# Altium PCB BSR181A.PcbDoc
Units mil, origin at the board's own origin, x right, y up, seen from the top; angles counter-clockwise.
Board outline 2710.5 x 1796.5 mil, 4 copper layers (Top Layer, Signal Layer 1, Signal Layer 2, Bottom Layer), stack 60.434 mil thick; 45 components, 12 nets, 61 pads, 44 vias.
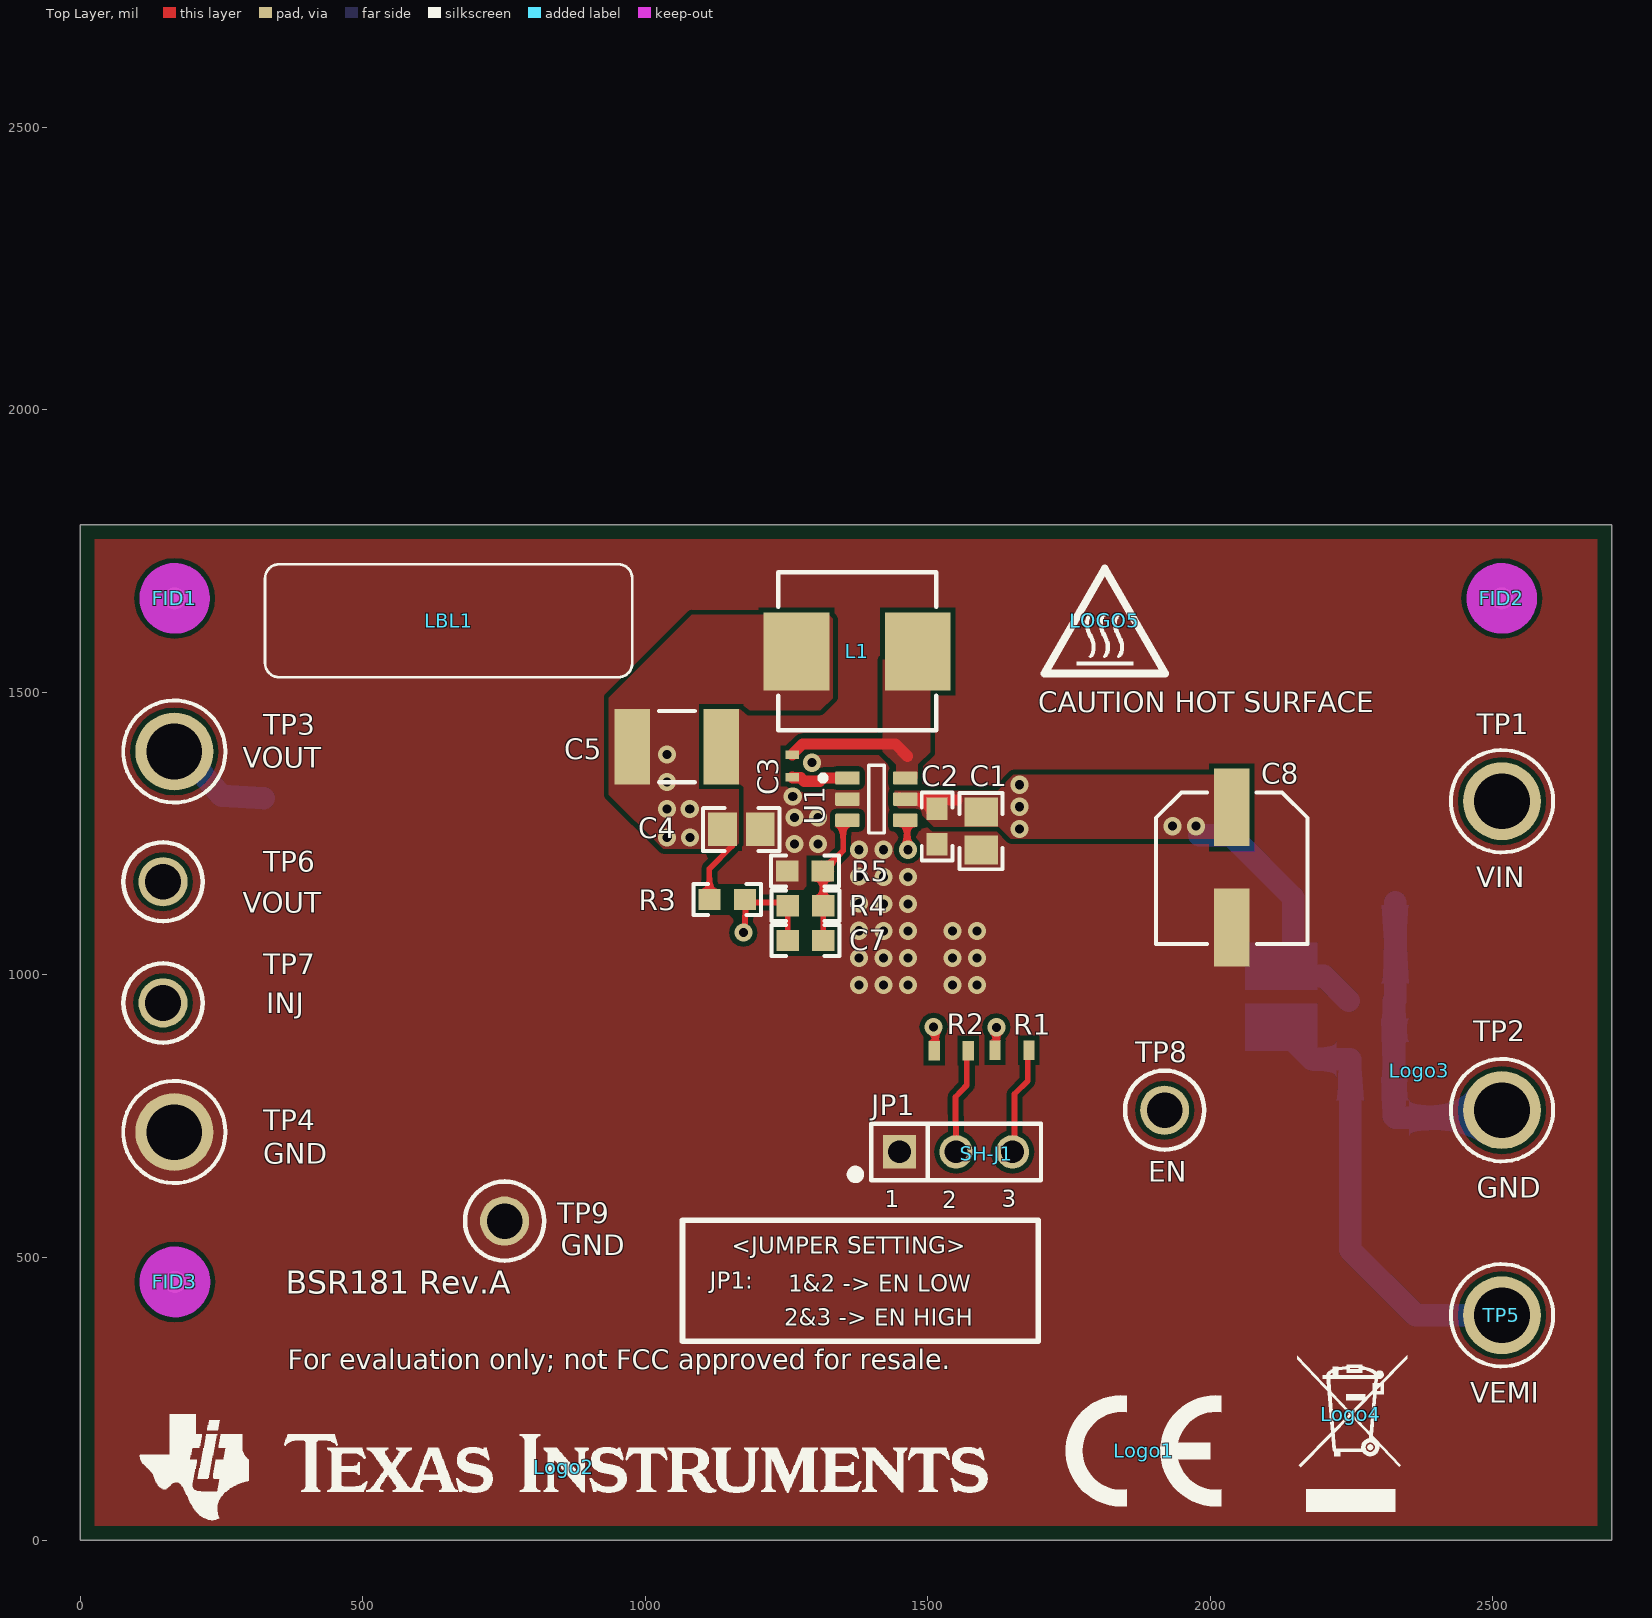
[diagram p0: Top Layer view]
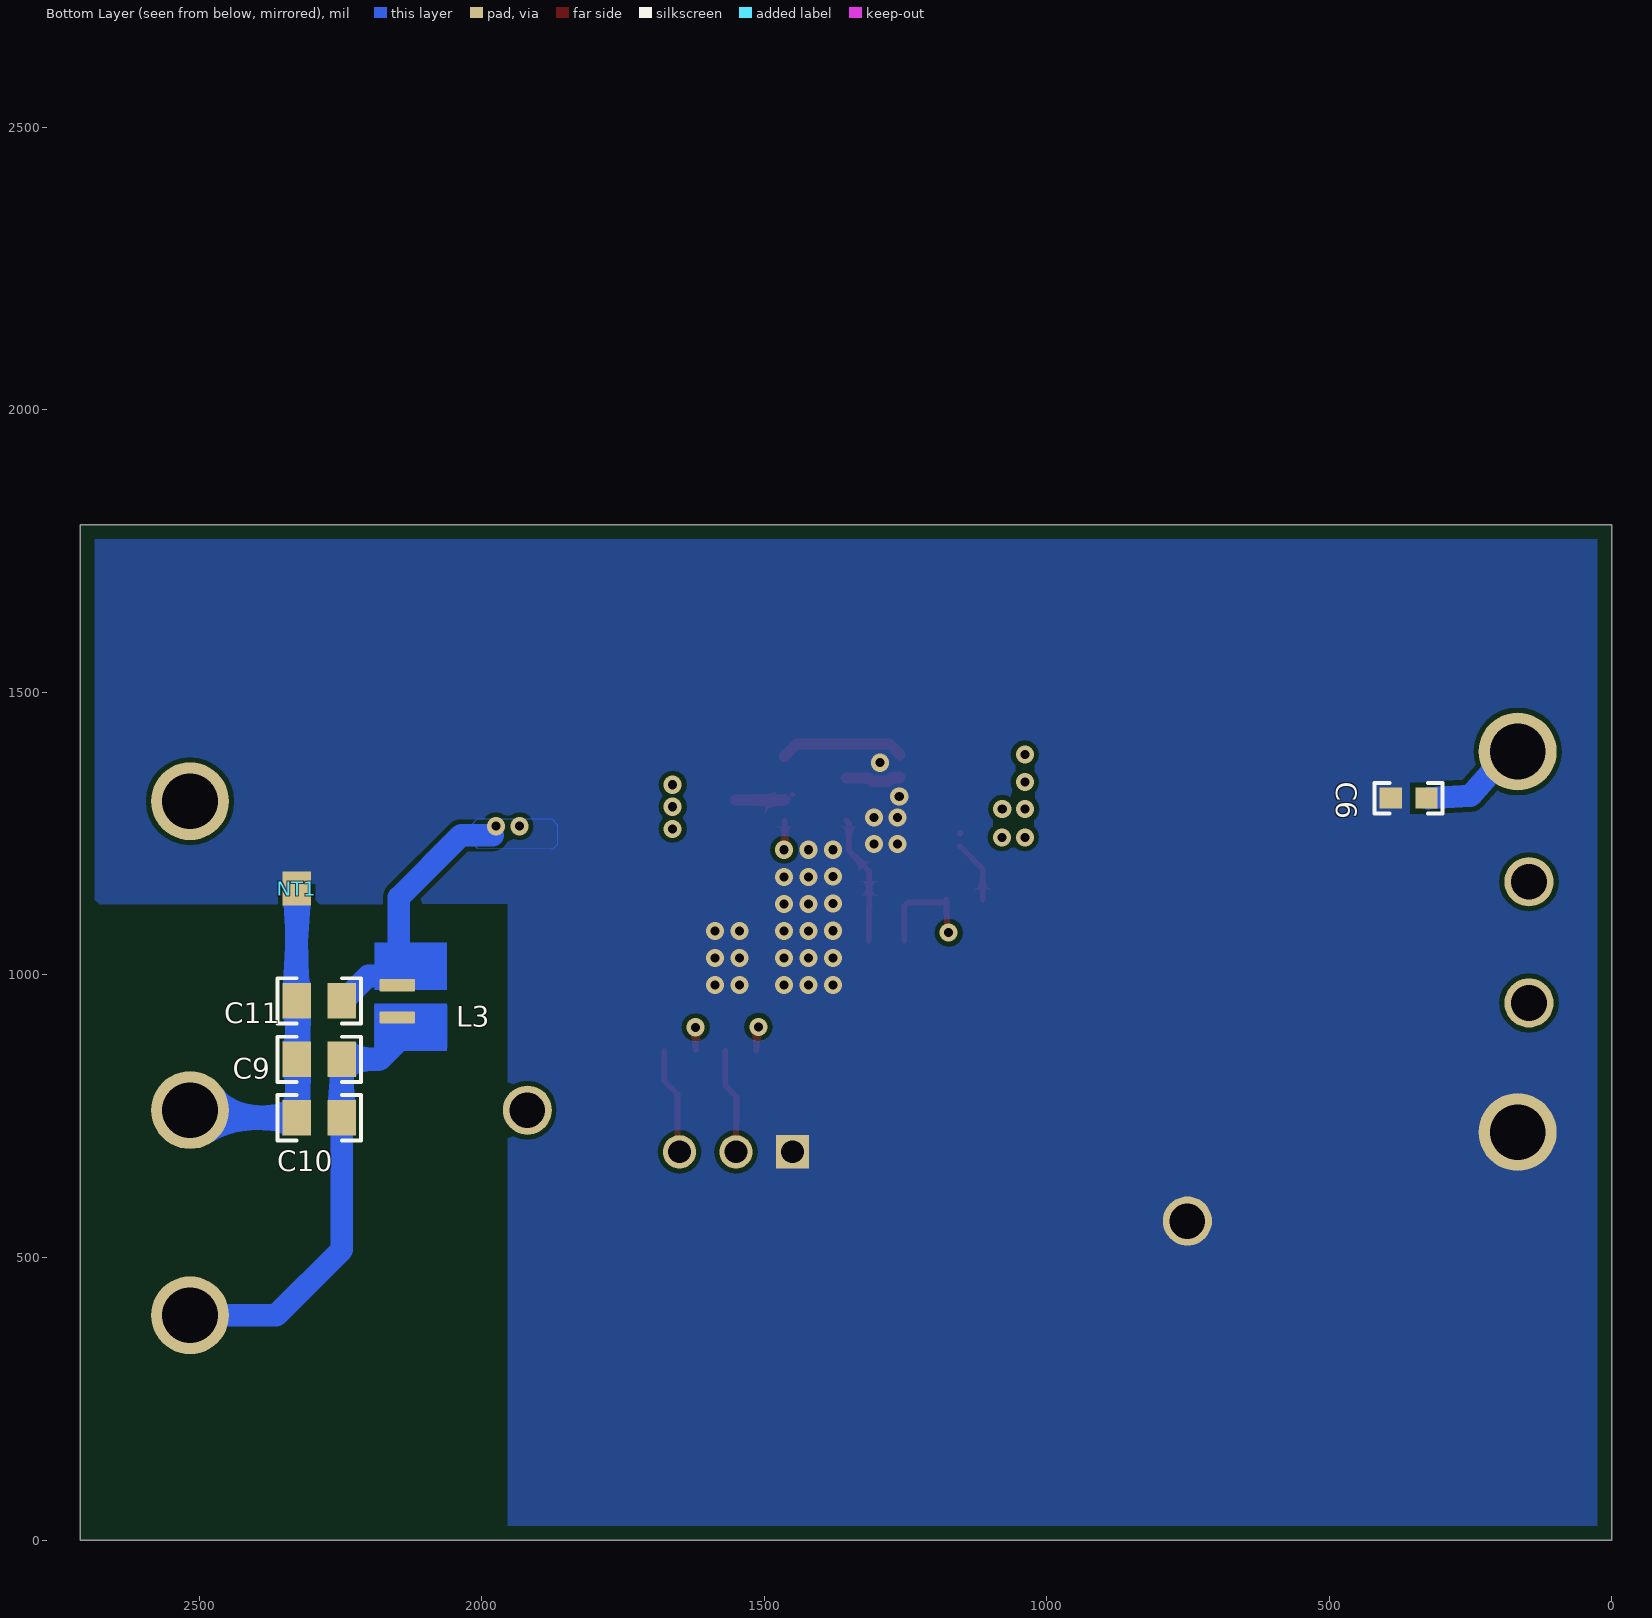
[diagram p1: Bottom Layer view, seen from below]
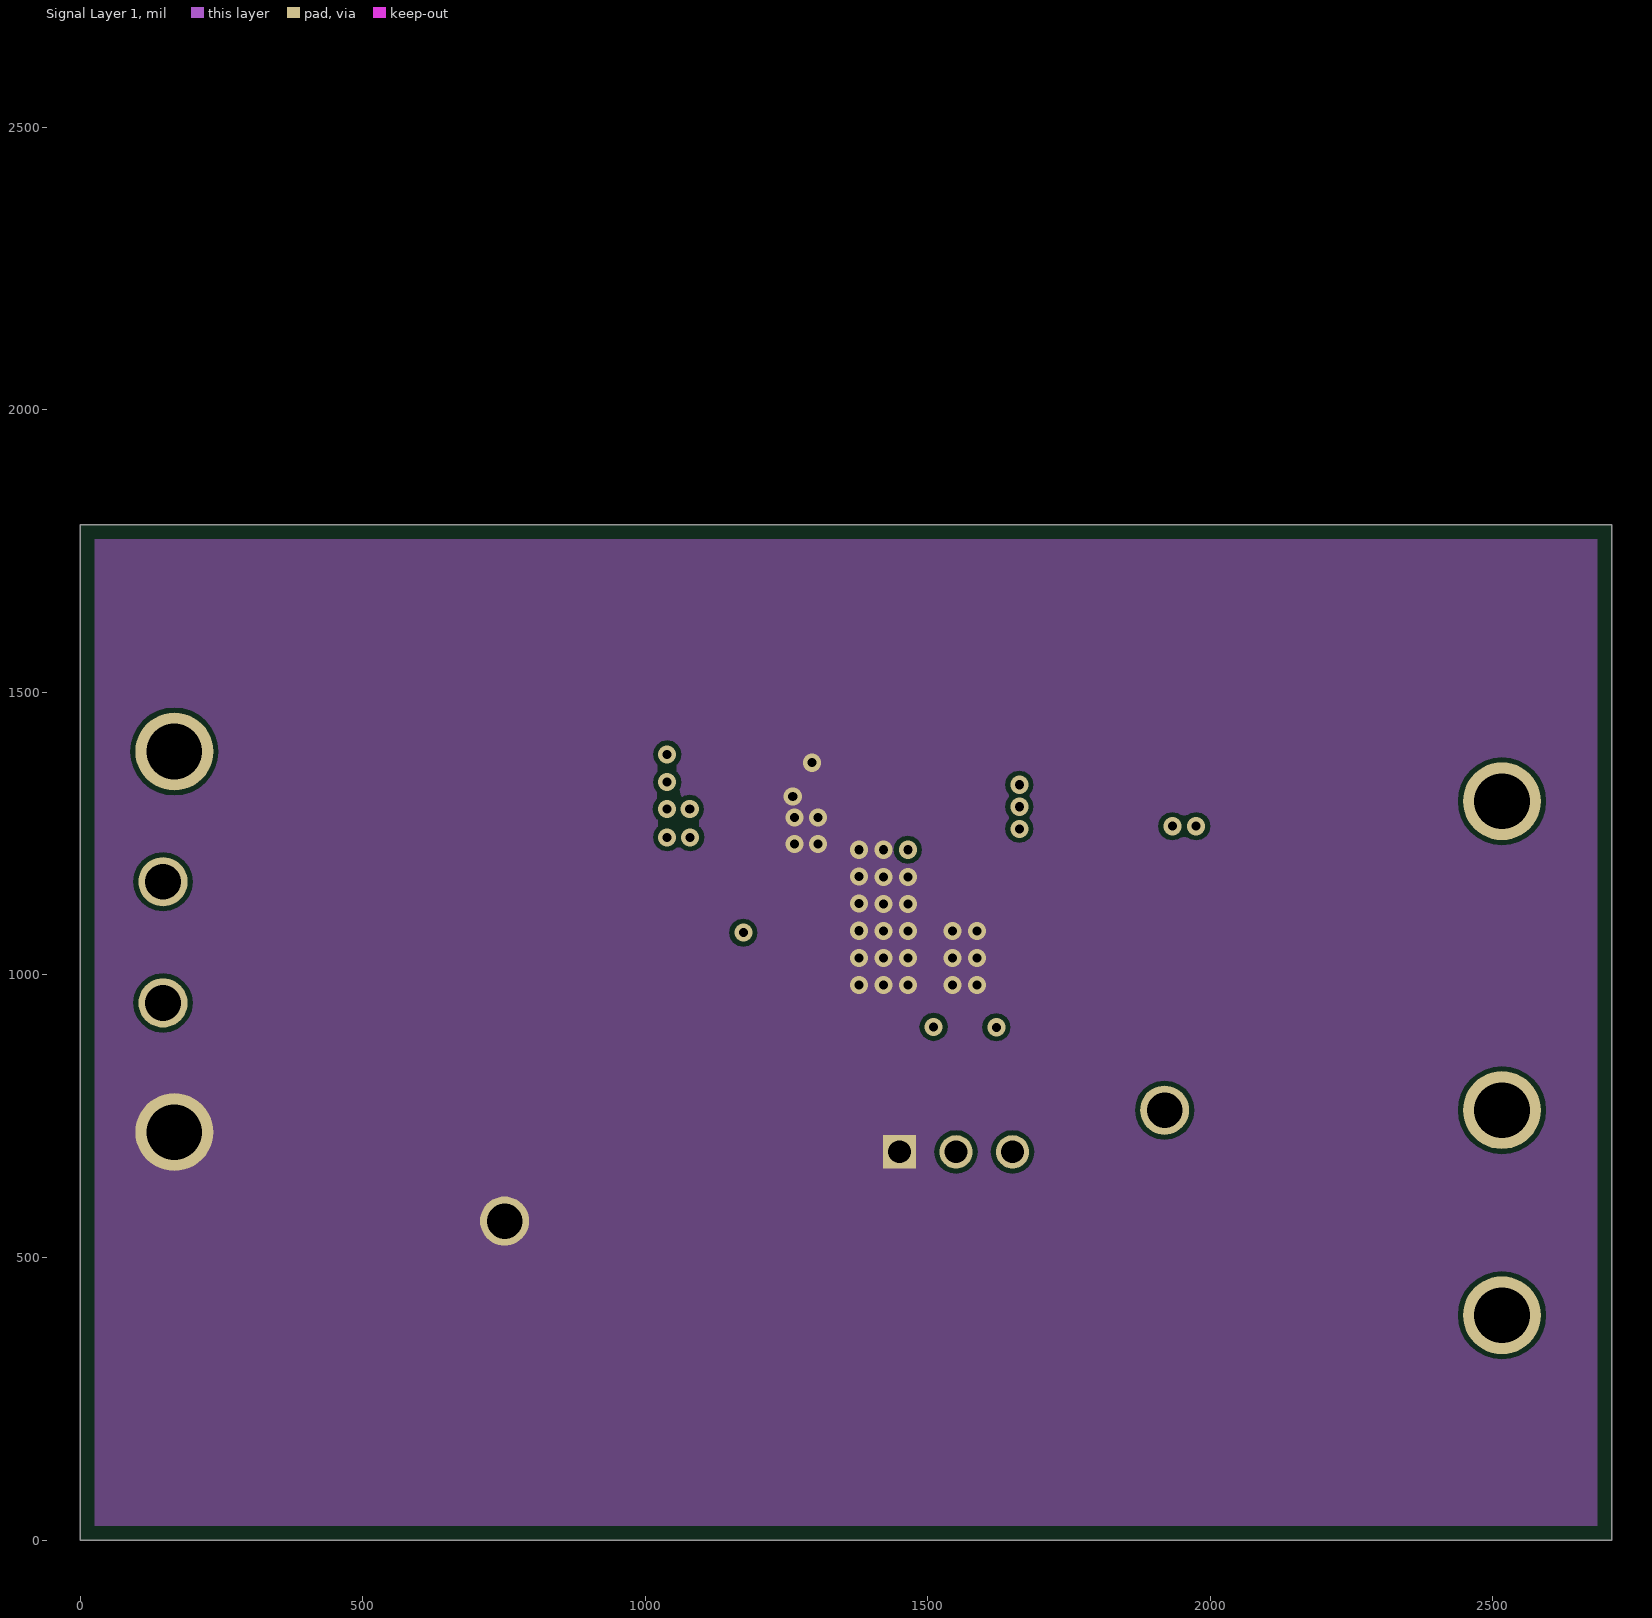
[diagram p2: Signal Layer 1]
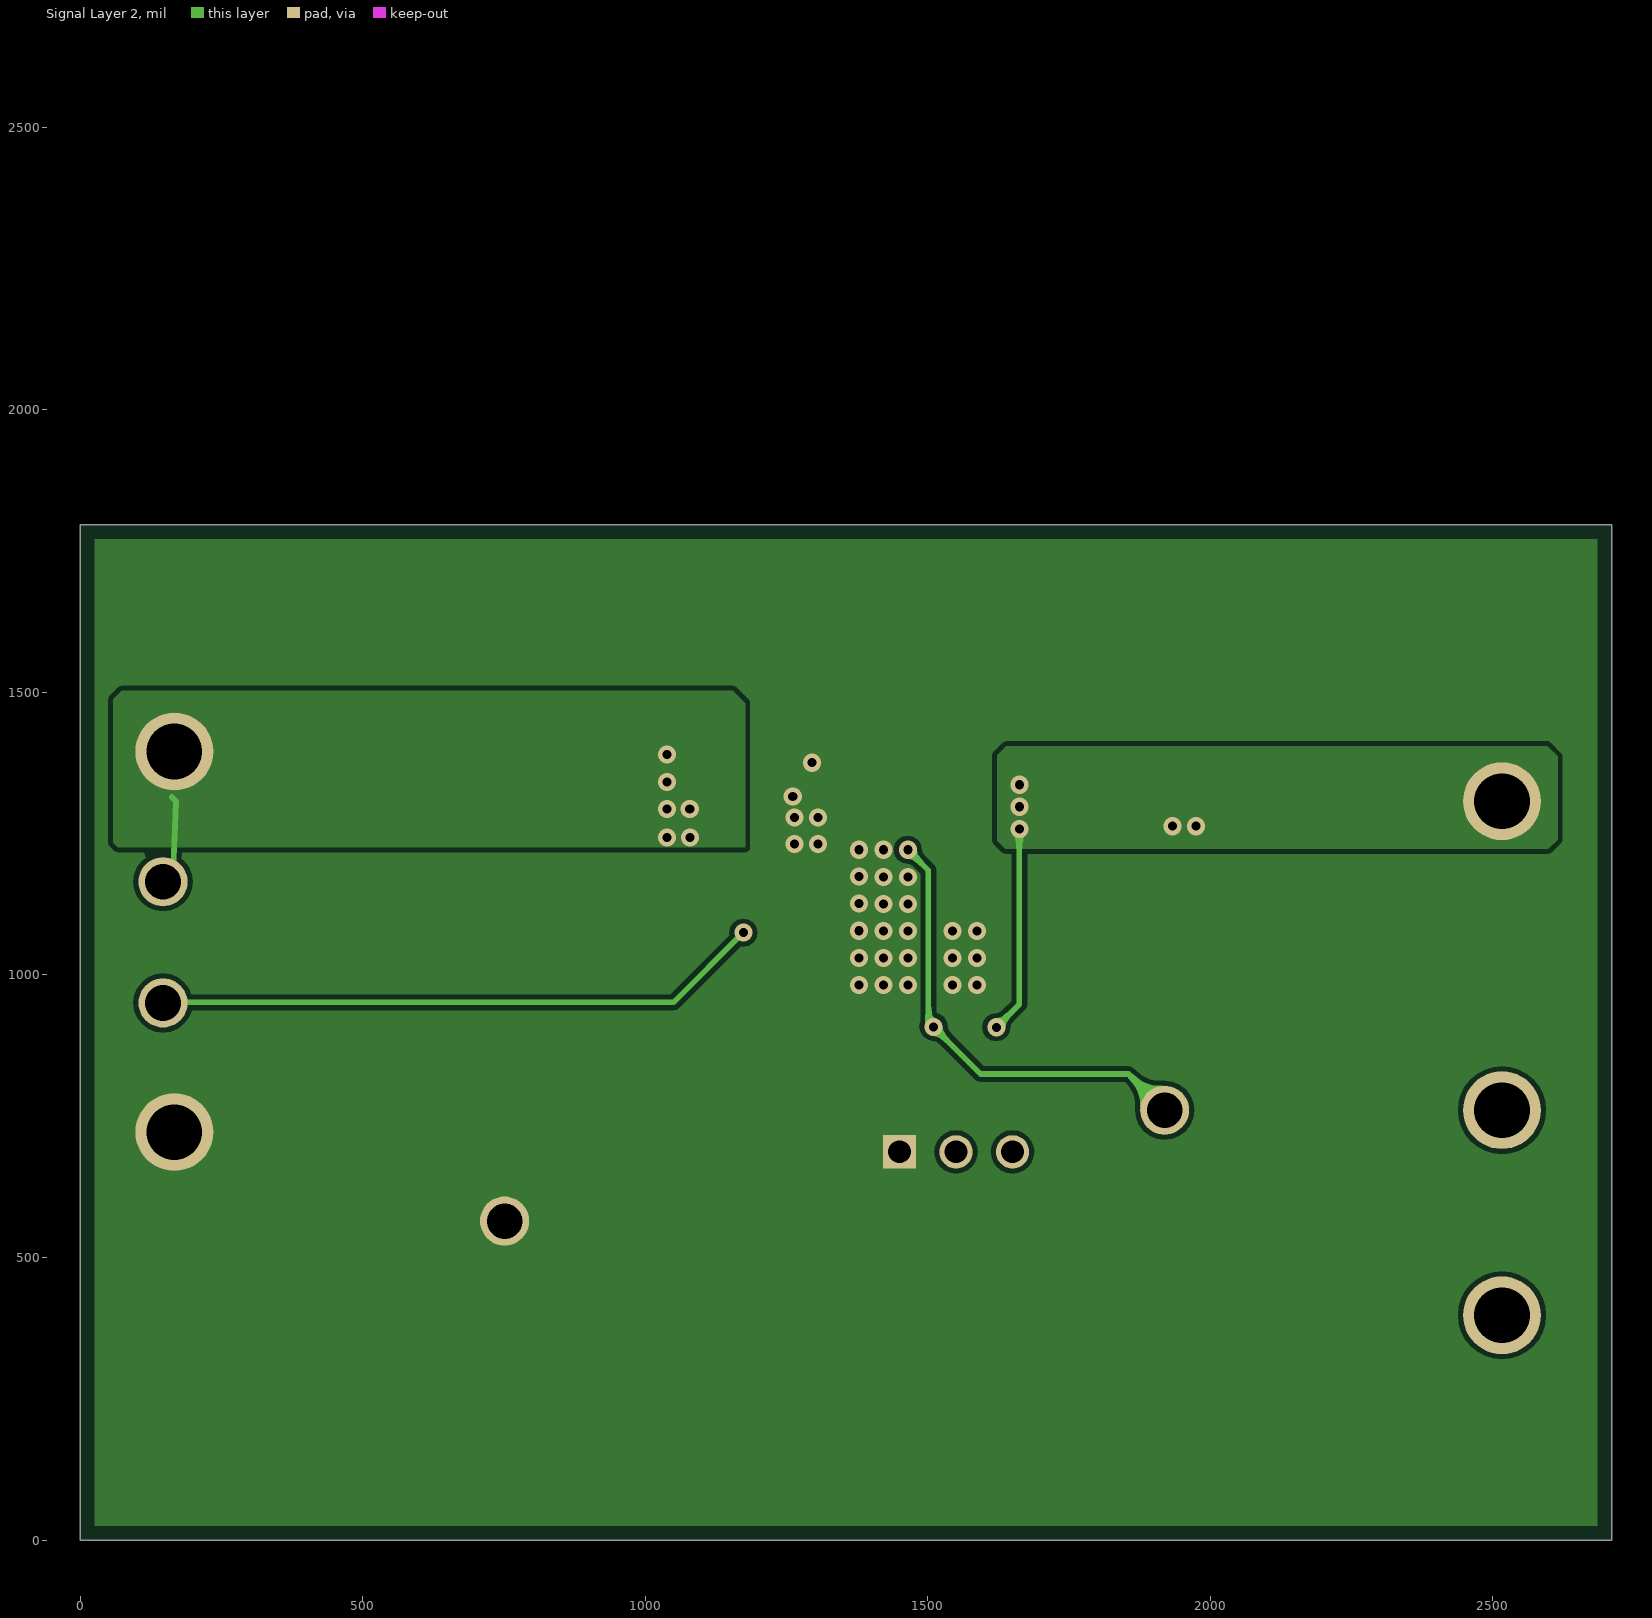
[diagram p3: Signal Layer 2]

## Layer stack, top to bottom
Top Solder: solder mask 0.4, Solder Resist, Dk 3.5
Top Layer: signal copper 2.8
Dielectric1: core 10, FR-4 High Tg, Dk 4.8
Signal Layer 1: signal copper 1.417
Dielectric 2: dielectric 32, FR-4 High Tg, Dk 4.2
Signal Layer 2: signal copper 1.417
Dielectric 3: dielectric 10, FR-4 High Tg, Dk 4.2
Bottom Layer: signal copper 2.8
Bottom Solder: solder mask 0.4, Solder Resist, Dk 3.5

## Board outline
0,0 0,1796.5 2710.5,1796.5 2710.5,0

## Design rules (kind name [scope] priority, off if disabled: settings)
AcuteAngle [All] p1: minimum=4.50000000000000E+0001 checktracksonly=FALSE
AssemblyTestPointUsage [All] p1: valid=2
BoardOutlineClearance BoardOutlineClearance_MountingHoles [OnCopper and InComponentClass('Mounting Holes')] p1: gap=40 ignorepadtopadclearanceinfootprint=FALSE
BoardOutlineClearance BoardOutlineClearance_Poly [OnCopper and IsPoly] p2: gap=25 ignorepadtopadclearanceinfootprint=FALSE
BoardOutlineClearance [OnCopper and Not InComponentClass('Logo') and not InComponentClass('FiducialMark') and not InRegion(1000,500,4000,800) and not InPoly] p3: gap=75 ignorepadtopadclearanceinfootprint=FALSE
Clearance Clearance_Keepouts [((IsTrack Or IsArc) And Not InPoly) And IsFree and IsKeepOut vs ((IsTrack Or IsArc) And Not InPoly) And IsFree and IsKeepOut] p1: gap=7 ignorepadtopadclearanceinfootprint=FALSE
Clearance Clearance_Poly [InPolygon] p2: gap=8.5 ignorepadtopadclearanceinfootprint=FALSE except(0: Arc-Hole Track-Hole SMDPad-Hole THPad-Hole Via-Hole Fill-Hole Poly-Hole Region-Hole Text-Hole)
Clearance [All] p3: gap=7 ignorepadtopadclearanceinfootprint=FALSE except(0: Arc-Arc Arc-Track Arc-SMDPad Arc-THPad Arc-Via Arc-Fill Arc-Poly Arc-Region Arc-Text Arc-Hole)
ComponentClearance ComponentClearance_MountingHoles_FiducialMarks [InComponentClass('Mounting Holes') vs InComponentClass('FiducialMark')] p1: gap=50 collisioncheckmode=3 verticalgap=10 showdistances=FALSE
ComponentClearance ComponentClearance_Shunt [InComponentClass('Header') vs InComponentClass('Shunt')] p2: gap=0 collisioncheckmode=3 verticalgap=0 showdistances=FALSE
ComponentClearance ComponentClearance_Logo [InComponentClass('Logo')] p3: gap=50 collisioncheckmode=3 verticalgap=10 showdistances=FALSE
ComponentClearance ComponentClearance_ScrewToNut [(HasFootprint('NY PMS 440 0025 PH')) vs (HasFootprint('Keystone_1902C'))] p4: gap=5 collisioncheckmode=3 verticalgap=10 showdistances=FALSE
ComponentClearance ComponentClearance_MountingHoles [InComponentClass('Mounting Holes')] p5: gap=250 collisioncheckmode=3 verticalgap=100000 showdistances=FALSE
ComponentClearance ComponentClearance_SmallPassives [HasFootprint('0201*') or HasFootprint('0402*') or HasFootprint('0508') or HasFootprint('0603*') or HasFootprint('0612') or HasFootprint('0805*') or HasFootprint('0815*') or HasFootprint('0830*') or HasFootprint('1206*') or HasFootprint('1210*') or HasFootprint('1808*') or HasFootprint('1812*') or HasFootprint('1825*') or HasFootprint('2010*') or HasFootprint('2220*') or HasFootprint('2225*') or HasFootprint('2512*') or HasFootprint('2728*') or HasFootprint('3518*') vs HasFootprint('0201*') or HasFootprint('0402*') or HasFootprint('0508') or HasFootprint('0603*') or HasFootprint('0612') or HasFootprint('0805*') or HasFootprint('0815*') or HasFootprint('0830*') or HasFootprint('1206*') or HasFootprint('1210*') or HasFootprint('1808*') or HasFootprint('1812*') or HasFootprint('1825*') or HasFootprint('2010*') or HasFootprint('2220*') or HasFootprint('2225*') or HasFootprint('2512*') or HasFootprint('2728*') or HasFootprint('3518*')] p6: gap=14.96 collisioncheckmode=3 verticalgap=10 showdistances=FALSE
ComponentClearance ComponentClearance_THtoSMT [IsThruComponent vs IsSMTComponent] p7: gap=10 collisioncheckmode=3 verticalgap=30 showdistances=FALSE
ComponentClearance ComponentClearance_THtoTH [IsThruComponent vs IsThruComponent] p8: gap=30 collisioncheckmode=3 verticalgap=30 showdistances=FALSE
ComponentClearance [All] p9: gap=30 collisioncheckmode=3 verticalgap=10 showdistances=FALSE
DiffPairsRouting [All] p1: maxlimit=100 minlimit=10 mostfreqgap=10 toplayer_minwidth=15 toplayer_maxwidth=15 toplayer_prefwidth=15 midlayer1_minwidth=15 midlayer1_maxwidth=15 midlayer1_prefwidth=15 midlayer2_minwidth=15 midlayer2_maxwidth=15 midlayer2_prefwidth=15 bottomlayer_minwidth=15 bottomlayer_maxwidth=15 bottomlayer_prefwidth=15 maxuncoupledlength=1000
FabricationTestPointUsage TestPointUsage [All] p1: valid=2 allowmultiple=FALSE
FabricationTestpoint Testpoint [All] p1: side=3 testpointundercomponent=TRUE minsize=40 maxsize=100 preferedsize=60 minholesize=0 maxholesize=40 preferedholesize=32 testpointgrid=1 allowsidetop=TRUE allowsidebottom=TRUE usegrid=TRUE gridtolerance=0.01
FanoutControl Fanout_LCC [IsLCC] p1: bgadir=Out bgaviamode=Centered fanoutstyle=Auto fanoutdirection=Alternating viagrid=1 // Fanout_LCC (Default Rule)
FanoutControl Fanout_BGA [IsBGA] p2: bgadir=Out bgaviamode=Centered fanoutstyle=Auto fanoutdirection=Alternating viagrid=1 // Fanout_BGA (Default Rule)
FanoutControl Fanout_Default [All] p4: bgadir=Out bgaviamode=Centered fanoutstyle=Auto fanoutdirection=Alternating viagrid=1 // Fanout_Default (Default Rule)
FanoutControl Fanout_Small [(CompPinCount < 5)] p5: bgadir=Out bgaviamode=Centered fanoutstyle=Auto fanoutdirection=OutThenIn viagrid=1 // Fanout_Small (Default Rule)
HoleSize [All] p1: absolutevalues=TRUE maxlimit=251 minlimit=7.87 maxpercent=80.000 minpercent=20.000
MinimumAnnularRing MinimumAnnularRing_ThermalPadVias [IsVia and InAnyComponent] p1: minimumring=5.91
MinimumAnnularRing [All] p2: minimumring=8
MinimumSolderMaskSliver MinimumSolderMaskSliver_Logo [InComponentClass('Logo') vs InComponentClass('Logo')] p1: minsoldermaskwidth=0.7
MinimumSolderMaskSliver [All] p2: minsoldermaskwidth=3.94
PlaneClearance [All] p1: clearance=0
PlaneConnect [All] p1: planeconnectstyle=Direct reliefexpansion=10 reliefentries=2 reliefconductorwidth=10 reliefairgap=10
PolygonConnect [All] p1: connectstyle=Direct reliefconductorwidth=10 reliefentries=4 polygonreliefangle="90 Angle" airgapwidth=10
RoutingVias ThermalPadVias [IsVia and InAnyComponent] p1: holewidth=7.87 width=19.68 viastyle="Through Hole" minholewidth=7.87 minwidth=19.68 maxholewidth=12.99 maxwidth=23.62
RoutingVias [All] p2: holewidth=16 width=34 viastyle="Through Hole" minholewidth=7.87 minwidth=26 maxholewidth=40 maxwidth=65
SilkToBoardRegionClearance [Not ((IsComment or IsDesignator) And (Hide <> 'False')) and not InRegion(1000,500,4000,800)] p1:
SilkToSilkClearance SilkToSilkClearance_Pb-FreeLogo [(HasFootprint('Pb-Free_Overlay_Medium') OR HasFootprint('Pb-Free_Overlay_Small')) vs (HasFootprint('Pb-Free_Overlay_Medium') OR HasFootprint('Pb-Free_Overlay_Small'))] p1: silktosilkclearance=0
SilkToSilkClearance [All] p2: silktosilkclearance=4
SilkToSolderMaskClearance SilkToComponentPadClearance [(IsPad or IsFill or IsRegion) and InAnycomponent] p1: minsilkscreentomaskgap=2 clearancetoexposedcopper=TRUE
SilkToSolderMaskClearance "Silk to Solder Mask Opening" [All] p2: minsilkscreentomaskgap=0.5 clearancetoexposedcopper=TRUE
SolderMaskExpansion [All] p1: expansion=1.85
Width [All] p1: maxlimit=100 minlimit=3 preferedwidth=10 midlayer1_minwidth=6 midlayer2_minwidth=6 bottomlayer_minwidth=6 minimp=50.000000 maximp=50.000000 favimp=50.000000 checkconnectedcopper=TRUE
14 further rules are at their usual default settings.

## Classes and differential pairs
component class Label: LBL1
component class Shunt: SH-J1
component class FiducialMark: FID1 FID2 FID3
component class BSR181A_Hardware: FID1 FID2 FID3 LBL1 Logo1 Logo2 Logo3 Logo4 LOGO5 LOGO7 SH-J1 ZZ1 ZZ2 ZZ3 ZZ4 ZZ5
component class Logo: Logo2
component class Header: JP1
component class AssemblyNote: ZZ1 ZZ2 ZZ3 ZZ4 ZZ5

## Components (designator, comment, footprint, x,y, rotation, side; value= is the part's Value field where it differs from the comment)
C1 "CGA4J3X7R1H225K125AB" 0805 1594.5,1254.74 r270 top value=2.2uF
C2 "GCM188R71H104KA57D" 0603 1516.52,1262.74 r270 top value=0.1uF
C3 "GRM155R71E104KE14D" 0402S 1259.92,1369.77 r270 top value=0.1uF
C4 "GRM21BZ71E106KE15L" 0805 1170,1257.74 r0 top value=10uF
C5 "CGA8P1X7R1E226M250KC" 1812_280 1055.74,1404.24 r0 top value=22uF
C6 "C1608X7R1E104K080AA" 0603 359.5,1313 r0 bottom value=0.1uF
C7 "GRM1885C1H220JA01D" 0603 1283.5,1061 r180 top value=22pF
C8 "EMVY500ADA470MF80G" CAPSMT_62_F80 2038,1190.54 r270 top value=47uF
C9 "CGA4J3X7R1H225K125AB" 0805_HV 2287.5,850.74 r0 bottom value=2.2uF
C10 "CGA4J3X7R1H225K125AB" 0805_HV 2287.5,747.24 r0 bottom value=2.2uF
C11 "CGA4J3X7R1H225K125AB" 0805_HV 2287.5,954.24 r0 bottom value=2.2uF
FID1 "Fiducial" Fiducial10-30 167,1666.5 r0 top
FID2 "Fiducial" Fiducial10-30 2516,1666.5 r0 top
FID3 "Fiducial" Fiducial10-30 167.5,456.74 r0 top
JP1 "PEC03SAAN" CONN_PEC03SAAN 1550.02,687 r0 top
L1 "74437349150" WE-LHMI_7050 1375,1572.83 r180 top value=15uH
L3 "DFE201612E-1R0M=P2" DFE201612E 2149.5,953.24 r90 bottom value=1uH
LBL1 "THT-14-423-10" Label_650x200 652,1627 r0 top
Logo1 "CE Mark" CE_Mark_5mm 1882,157.74 r0 top
Logo2 "Texas Instruments" TI_Horizontal_Overlay_Medium 855.5,128.74 r0 top
Logo3 "FCC disclaimer" FCC_disclaimer 2370,830.74 r90 top
Logo4 "WEEE logo" WEEE_Minimum 2249,222.5 r0 top
LOGO5 "CAUTION HOT SURFACE" IEC_HotSurface_Small 1813.25,1626.83 r0 top
NT1 "Net-Tie" Net-Tie_50milWide_30milLong 2327.5,1153 r90 bottom net-tie
R1 "CRCW0603402KFKEA" 0603S 1649.02,866.74 r180 top value=402k
R2 "CRCW0603133KFKEA" 0603S 1541.44,866.04 r0 top value=133k
R3 "Resistor" 0603 1145,1133.74 r0 top value=49.9
R4 "RT0603BRD0770K6L" 0603 1283.5,1122.54 r180 top value=70.6k
R5 "RC0603FR-0722K1L" 0603 1282.81,1184.07 r0 top value=22.1k
SH-J1 "SNT-100-BK-G" SNT-100-BK-G 1604.5,684 r180 top value=1x2
TP1 "1502-2" Keystone1502-2 2516.24,1307.54 r0 top
TP2 "1502-2" Keystone1502-2 2516.24,760.8 r0 top
TP3 "1502-2" Keystone1502-2 166.5,1395.5 r0 top
TP4 "1502-2" Keystone1502-2 166.5,722 r0 top
TP5 "1502-2" Keystone1502-2 2516.24,397.74 r0 top
TP6 "5010" Keystone5010 146.44,1165 r0 top
TP7 "5014" Keystone5014 146.44,950.5 r0 top
TP8 "5014" Keystone5014 1919.24,760.74 r0 top
TP9 "5011" Keystone5011 751,564.5 r0 top
U1 "LMR54410DBVR" DBV0006A-MFG 1409.02,1311.24 r0 top
ZZ1 "This Assembly Note is for PCB labels only" AssemblyNoteLabel 197,3292.5 r0 top
ZZ2 "These assemblies are ESD sensitive, ESD precautions shall be observed." AssemblyNote 197,3169.5 r0 top
ZZ3 "These assemblies must be clean and free from flux and all contaminants. Use of no clean flux is not acceptable." AssemblyNote 197,3046 r0 top
ZZ4 "These assemblies must comply with workmanship standards IPC-A-610 Class 2, unless otherwise specified." AssemblyNote 197,2913.5 r0 top
ZZ5 "SH-J1 should be put in the 2 & 3 pin of JP1 by default." AssemblyNote 197,2800.5 r0 top

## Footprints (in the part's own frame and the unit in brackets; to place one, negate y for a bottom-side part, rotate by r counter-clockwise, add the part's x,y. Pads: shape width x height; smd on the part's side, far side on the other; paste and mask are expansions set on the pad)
0402S [mil] "Based on C0402S footprint from PADS legacy"
  rect 15x24 smd: 1(-20,0) 2(20,0)
  body extent -22,-12 22,12, height 24
0603 [mm] "0603 from SM-752 data"
  rect 1x0.95 smd: 1(-0.8,0) 2(0.8,0)
  silkscreen extent -1.52,-0.69 1.52,0.69, body extent -0.87,-0.47 0.87,0.47, height 1
0603S [mil]
  rect 20x35 smd: 1(-30,0) 2(30,0)
  body extent -34,-19 34,19, height 39
0805 [mm] "0805 from SM-752 data"
  rect 1.3x1.5 smd: 1(-0.85,0) 2(0.85,0)
  silkscreen extent -1.72,-0.97 1.72,0.97, body extent -1.1,-0.72 1.1,0.72, height 1.45
0805_HV [mil] "0805 with 30mil clearance between pads"
  rect 50x63 smd: 1(-40,0) 2(40,0)
  silkscreen extent -74,-40 74,40, body extent -43,-29 43,29, height 57
1812_280 [mm] "1812"
  rect 1.6x3.4 smd: 1(-2,0) 2(2,0)
  silkscreen extent -0.8,-1.6 0.8,1.6, body extent -2.4,-1.7 2.4,1.7, height 2.8
AssemblyNote [mil] "Assembly Note"
AssemblyNoteLabel [mil] "Assembly Note for PCB Labels"
CAPSMT_62_F80 [mm] "6.3 x 7.7mm:  Chemi-Con F80"
  rect 3.5x1.6 smd: 1(-2.7,0) 2(2.7,0)
  silkscreen extent -3.36,-3.4 3.44,3.4, body extent -3.4,-3.4 3.44,3.4, height 8
CE_Mark_5mm [mil] "Minimum text height for CE Mark"
  silkscreen extent -138,-98 138,98
CONN_PEC03SAAN [mm] "SULLINS"
  rect 1.5x1.5 hole 1.016: 1(-2.54,0)
  round 1.5 hole 1.016: 2(0,0) 3(2.54,0)
  silkscreen extent -4.72,-1.27 3.81,1.27, body extent -3.84,-1.3 3.84,1.3, height 8.38
DBV0006A-MFG [mm]
  rrect17% 1.1x0.6 smd paste+0 mask+0: 1(-1.3,0.95) 2(-1.3,0) 3(-1.3,-0.95) 4(1.3,-0.95) 5(1.3,0) 6(1.3,0.95)
  silkscreen extent -2.52,-1.53 0.35,1.53, body extent -1.95,-1.78 1.95,1.78, height 0.25
DFE201612E [mm] "MuRata recommended"
  rrect18% 0.55x1.6 smd: 1(-0.725,0) 2(0.725,0)
  body extent -1.1,-0.9 1.1,0.9, height 1.2
FCC_disclaimer [mil]
Fiducial10-30 [mm]
  round 1 smd mask+1: 1(0,0)
  Top Layer keep-out circle w1.678: c0,0 r0.75
IEC_HotSurface_Small [mil]
  silkscreen extent -107,-93 107,92
Keystone1502-2 [mm] "Double Turret"
  round 3.5 hole 2.5: 1(0,0)
  silkscreen extent -2.3,-2.3 2.3,2.3, body extent -1.6,-1.6 1.59,1.6, height 5.62
Keystone5010 [mil] "Keystone Multipurpose loops"
  round 87 hole 63: 1(0,0)
  silkscreen extent -70,-70 70,70, body extent -63,-63 63,62, height 319
Keystone5011 [mil] "Keystone Multipurpose loops"
  round 87 hole 63: 1(0,0)
  silkscreen extent -70,-70 70,70, body extent -63,-63 63,62, height 319
Keystone5014 [mil] "Keystone Multipurpose loops"
  round 87 hole 63: 1(0,0)
  silkscreen extent -70,-70 70,70, body extent -63,-63 63,62, height 319
Label_650x200 [mil] "Thermal Transfer Label"
  round 1 on Mech13: 0(0,0)
  silkscreen extent -325,-100 325,100, body extent -325,-100 325,100, height 1
Net-Tie_50milWide_30milLong [mil] "50mil net tie, no solder mask opening, no solder paste"
  rect 30x50 smd paste-20 mask-20: 1(-15,0) 2(15,0)
SNT-100-BK-G [mil] "Samtec STEP model"
  round 1 on Mech3: 0(0,0)
  body extent -100,-50 100,50, height 344
TI_Horizontal_Overlay_Medium [mil]
  silkscreen extent -750,-94 750,94
WE-LHMI_7050 [mm] "Wurth"
  rect 2.95x3.5 smd: 1(-2.725,0) 2(2.725,0)
  silkscreen extent -3.55,-3.55 3.55,3.55, body extent -3.8,-3.45 3.8,3.45, height 5
WEEE_Minimum [mil] "WEEElie bin"
  silkscreen extent -95,-172 99,104

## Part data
C1 C9 C10 C11: library part CMP-0007977-2, "CAP, CERM, 2.2 uF, 50 V, +/- 10%, X7R, AEC-Q200 Grade 1, 0805", Cap_Case=0805, Manufacturer=TDK, Supplier Part Number 1=445-174216-1-ND, TempCo=X7R, Tolerance_%=10%, Value1="0.003288 ohm", Value2=50V, ValueDisplayed=2.2uF
C2: library part CMP-0007144-2, "CAP, CERM, 0.1 uF, 50 V, +/- 10%, X7R, 0603", Cap_Case=0603, Manufacturer=MuRata, Supplier Part Number 1=490-4779-1-ND, TempCo=X7R, Tolerance_%=10%, Value1="0.02 ohm", Value2=50V, ValueDisplayed=0.1uF
C3: library part CMP-0006659-1, "CAP, CERM, 0.1 uF, 25 V, +/- 10%, X7R, 0402", Cap_Case=0402, Manufacturer=MuRata, Supplier Part Number 1=490-10698-1-ND, TempCo=X7R, Tolerance_%=10%, Value1=Unknown, Value2=25V, ValueDisplayed=0.1uF
C4: library part CMP-0008378-2, "CAP, CERM, 10 uF, 25 V, +/- 10%, X7R, 0805", Cap_Case=0805, Manufacturer=MuRata, Supplier Part Number 1=81-GRM21BZ71E106KE5L, TempCo=X7R, Tolerance_%=10%, Value1=Unknown, Value2=25V, ValueDisplayed=10uF
C5: library part CMP-0009402-2, "CAP, CERM, 22 uF, 25 V, +/- 20%, X7R, AEC-Q200 Grade 1,", Cap_Case=1812_280, Manufacturer=TDK, Supplier Part Number 1=445-7910-1-ND, TempCo=X7R, Tolerance_%=20%, Value1="0.002434 ohm", Value2=25V, ValueDisplayed=22uF
C6: library part CMP-0007039-1, "CAP, CERM, 0.1 uF, 25 V, +/- 10%, X7R, 0603", Cap_Case=0603, Manufacturer=TDK, Supplier Part Number 1=445-1316-1-ND, TempCo=X7R, Tolerance_%=10%, Value1=Unknown, Value2=25V, ValueDisplayed=0.1uF
C7: library part CMP-0007196-4, "CAP, CERM, 22 pF, 50 V, +/- 5%, C0G/NP0, 0603", Cap_Case=0603, Manufacturer=MuRata, Supplier Part Number 1=490-1411-1-ND, TempCo=C0G/NP0, Tolerance_%=5%, Value1=Unknown, Value2=50V, ValueDisplayed=22pF
C8: library part CMP-0011362-1, "CAP, AL, 47 uF, 50 V, +/- 20%, 0.6 ohm, SMD", Cap_Case=F80, Manufacturer=Chemi-Con, Supplier Part Number 1=565-2493-1-ND, Tolerance_%=20%, Value1="0.6 ohm", Value2=50V, ValueDisplayed=47uF
FID1 FID2 FID3: library part CMP-0077181-1, "Fiducial mark.  There is nothing to buy or mount.", Manufacturer=N/A
JP1: library part CMP-0002338-1, "Header, 100mil, 3x1, Tin, TH", Color=Black, Current_A=3A, Manufacturer="Sullins Connector Solutions", Supplier Part Number 1=S1012E-03-ND, Voltage_V=1.8kV
L1: library part CMP-0064491-2, "Inductor, Shielded Drum Core, Powdered Iron, 15 uH, 2.75 A, 0.092 ohm, SMD", Manufacturer="Wurth Elektronik", Supplier Part Number 1=710-74437349150, Value1="0.092 ohm", Value2=2.75A, ValueDisplayed=15uH
L3: library part CMP-0080773-1, "Inductor, Shielded, Metal Composite, 1 µH, 2.9 A, 0.048 ohm, SMD", Manufacturer=MuRata, PartNumber=DFE201612E-1R0M{}P2, Value1="0.048 ohm", Value2=2.9A, ValueDisplayed=1µH
LBL1: library part CMP-0003625-1, "Thermal Transfer Printable Labels, 0.650\" W x 0.200\" H - 10,000 per roll", Manufacturer=Brady, Supplier Part Number 1=97C5133
Logo1: library part CMP-0074844-1
Logo2: library part CMP-0074838-1, "Texas Instrument Corporate Signature"
Logo3: library part CMP-0074847-1, "FCC_disclaimer"
Logo4: library part CMP-0074769-1
LOGO5: library part CMP-0074837-1, "IEC 61010-1 Hot Surface Warning"
NT1: library part CMP-0078142-2, "Single point connection between nets.", Manufacturer=N/A
R1: library part CMP-0022408-4, "RES, 402 k, 1%, 0.1 W, AEC-Q200 Grade 0, 0603", Manufacturer=Vishay-Dale, Power_W=100mW, Supplier Part Number 1=541-402KHCT-ND, TempCo="100 ppm/C", Tolerance_%=1%, Value2=0.1W, Value_Code=402k
R2: library part CMP-0022038-4, "RES, 133 k, 1%, 0.1 W, AEC-Q200 Grade 0, 0603", Manufacturer=Vishay-Dale, Power_W=100mW, Supplier Part Number 1=541-133KHCT-ND, TempCo="100 ppm/C", Tolerance_%=1%, Value2=0.1W, Value_Code=133k
R3: library part CMP-0022448-3, "RES, 49.9, 1%, 0.1 W, 0603", Manufacturer=Vishay-Dale, PartNumber=CRCW060349R9FKEA, Power_W=100mW, Supplier Part Number 1=541-49.9HCT-ND, TempCo="100 ppm/C", Tolerance_%=1%, Value2=0.1W, Value_Code=49R9, ValueDisplayed=49.9
R4: library part CMP-0024444-2, "RES, 70.6 k, 0.1%, 0.1 W, 0603", Manufacturer="Yageo America", Power_W=100mW, TempCo="25 ppm/C", Tolerance_%=0.1%, Value2=0.1W, Value_Code=70k6, ValueDisplayed=70.6k
R5: library part CMP-0022923-5, "RES, 22.1 k, 1%, 0.1 W, 0603", Manufacturer=Yageo, Power_W=100mW, Supplier Part Number 1=311-22.1KHRCT-ND, TempCo="100 ppm/C", Tolerance_%=1%, Value2=0.1W, Value_Code=22k1, ValueDisplayed=22.1k
SH-J1: library part CMP-0003623-3, "Shunt, 100mil, Gold plated, Black", Alternate Manufacturer=3M, Alternate PartNumber=969102-0000-DA, Manufacturer=Samtec, Supplier Part Number 1=SAM8858-ND
TP1 TP2 TP3 TP4 TP5: library part CMP-0055113-1, "Terminal, Turret, TH, Double", Manufacturer=Keystone, Supplier Part Number 1=36-1502-2-ND
TP6: library part CMP-0055147-1, "Test Point, Multipurpose, Red, TH", Color=Red, Manufacturer=Keystone, Supplier Part Number 1=36-5010-ND
TP7 TP8: library part CMP-0055151-1, "Test Point, Multipurpose, Yellow, TH", Color=Yellow, Manufacturer=Keystone, Supplier Part Number 1=36-5014-ND
TP9: library part CMP-0055148-1, "Test Point, Multipurpose, Black, TH", Color=Black, Manufacturer=Keystone, Supplier Part Number 1=36-5011-ND
U1: library part CMP-0093105-2, "Buck Converter, Adjustable, 4V-36V Input, 1-28V 1A Output, SOT23-6", Manufacturer="Texas Instruments", Max Supply Voltage=36V, Min Supply Voltage=4V, Nominal Supply Current=80uA, Operating Temperature Range="-40°C to +150°C", Output Voltage=1-28V, Switching Frequency=700kHz
ZZ1: library part CMP-0003616-3
ZZ2: library part CMP-0077236-1
ZZ3: library part CMP-0077237-1
ZZ4: library part CMP-0077238-1
ZZ5: library part CMP-0077238-1, "These assemblies must comply with workmanship standards IPC-A-610 Class 2, unless otherwise specified."

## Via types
v1: diameter 32, hole 16, Top Layer to Bottom Layer, tented both sides, 44 vias

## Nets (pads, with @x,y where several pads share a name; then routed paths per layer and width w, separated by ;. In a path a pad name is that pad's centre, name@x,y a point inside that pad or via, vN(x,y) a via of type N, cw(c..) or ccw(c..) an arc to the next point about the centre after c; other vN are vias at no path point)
EN: R2.1 TP8.1 U1.4 | length 897.7
  Top Layer w10: U1.4@1463.4,1272.79 1463.4,1222.87 v1(1464.63,1221.64) ; v1(1510.25,908.04) 1513.88,904.4 R2.1@1513.88,866.04
  Signal Layer 2 w10: v1(1464.63,1221.64) 1501.13,1185.15 1501.13,917.16 v1(1510.25,908.04) 1593.55,824.74 1855.24,824.74 TP8.1
GND: C1.2 C2.2 C4.2 C5.2 C6.2 C8.2 JP1.1 NT1.2 R5.1 TP4.1 TP9.1 U1.2
  other v1: 1378.13,982.34 1421.38,982.34 1464.63,982.34 1543.88,982.34 1587.13,982.34 1378.13,1030.31 1421.38,1030.2 1464.63,1030.2 1543.88,1030.2 1587.13,1030.2 1378.13,1078.28 1421.38,1078.06 1464.63,1078.06 1543.88,1078.06 1587.13,1078.06 1378.13,1126.25 1421.38,1125.92 1464.63,1125.92 1378.13,1174.22 1421.38,1173.78 1464.63,1173.78 1378.13,1221.64 1421.38,1221.64 1263.83,1231.79 1305.33,1231.79 1263.83,1278.79 1305.33,1278.79 1261,1316 1294.92,1375.69
INJ: C7.2 R3.2 R4.2 TP7.1 | length 1249.9
  Top Layer w10: v1(1173.5,1075) 1176.5,1078 1177.43,1133.73 1182.86,1128.3 1246.24,1128.3 R4.2 C7.2
  Signal Layer 2 w10: TP7.1@175.5,951.5 957.5,951.5 1050,951.5 v1(1173.5,1075)
NetC3_2: C3.2 U1.1 | length 100.4
  Top Layer w20: C3.2 1260.69,1349 1274.94,1349 1281.25,1342.69 1308.59,1342.69 1314.54,1348.64 U1.1@1354.89,1348.64
NetC7_1: C7.1 R4.1 R5.2 U1.3 | length 224.1
  Top Layer w10: R4.1@1313.54,1122.54 1315,1121.08 C7.1 ; R4.1@1314.31,1128.68 R5.2 1350.13,1219.89 1350.13,1269.08 U1.3@1354.89,1273.84
NetC9_2: C9.2 C10.2 C11.2 NT1.1 TP2.1 | length 577.2
  Bottom Layer w40: C11.2@2325,954.24 2325,749.74 C10.2 2502.69,747.24 TP2.1 ; C11.2 NT1.1@2327.5,1129
NetJP1_2: JP1.2 R2.2 | length 187.1
  Top Layer w10: JP1.2 1549.09,784.11 1569,804.84 R2.2@1569,866.04
NetJP1_3: JP1.3 R1.1 | length 188.2
  Top Layer w10: JP1.3@1653.5,687.5 1653.5,789.34 1676.81,812.65 R1.1@1676.81,866.04
SW: C3.1 L1.1 U1.6 | length 221.1
  Top Layer w20: C3.1 1259.92,1390.27 1278.33,1408.69 1442.55,1408.69 1464,1387.24
VIN: C1.1 C2.1 C8.1 C11.1 L3.2 R1.2 TP1.1 U1.5 | length 956.8
  Top Layer w10: U1.5@1450.07,1318.79 U1.5@1450.24,1318.97 ; v1(1621.41,907.47) 1621.46,907.41 R1.2@1621.46,866.74
  Top Layer w20: U1.5@1463.4,1310.19 1463.81,1309.79 1551.13,1309.79
  Signal Layer 2 w10: v1(1621.41,907.47) 1662,948.06 v1@1662,1259.74
  Bottom Layer w40: 1980.5,1247.24 2036.5,1247.24 2146.5,1137.24 2146.5,1012.74 2161,998.24 2201,998.24 C11.1@2245,954.24
  other v1: 1662,1258.74 1932.82,1263.31 1974.94,1263.31 1662,1297.74 1662,1336.74
VIN_EMI_P: C9.1 C10.1 L3.1 TP5.1 | length 804.6
  Bottom Layer w40: L3.1@2149.5,922.73 2149.5,881.24 2180,850.74 C9.1 C10.1 2247.5,513.8 2363.56,397.74 TP5.1@2515,397.74
VOUT: C4.1 C5.1 C6.1 L1.2 R3.1 TP3.1 TP6.1 | length 456.7
  Top Layer w10: R3.1 1113.5,1188 1153.5,1228 ; C4.1@1152.1,1251.8 C4.1@1153.84,1250.05
  Signal Layer 2 w10: 162,1315 169.5,1307.5 163.39,1165 TP6.1@163.37,1164.5
  Bottom Layer w40: TP3.1@174,1403 174.41,1402.54 250.16,1317.38 C6.1@325.08,1313
  other v1: 1038.73,1243.59 1079.23,1243.59 1038.23,1293.74 1078.73,1293.74 1038.73,1341.25 1038.73,1390.27
pads on no net: FID1.1 FID2.1 FID3.1 LBL1.0 SH-J1.0

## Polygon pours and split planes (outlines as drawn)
GND on Top Layer "TOP_LAYER_GND_P095" (solid, remove dead copper, pour order 95): 0,0 0,1781.5 2695.5,1781.5 2702,1788 2702,0
VIN on Top Layer "TOP_LAYER_VIN_P010" (solid, remove dead copper, pour order 10): 1623.62,1326.29 1651.34,1354.24 2067.56,1354.24 2067.56,1241.01 1647.16,1241.01 1625.38,1262.8 1510.87,1262.8 1478.38,1295.29 1441.83,1295.29 1441.83,1326.29 1492.13,1326.29 1596.07,1326.29
VOUT on Top Layer "TOP_LAYER_VOUT_P036" (solid, remove dead copper, pour order 36): 1332,1637.33 1332,1490.24 1310,1468.24 1178,1468.24 1165,1455.24 1165,1233.06 1155.22,1223.27 1031.73,1223.27 935.66,1319.33 935.66,1490.64 1082.35,1637.33
SW on Top Layer "TOP_LAYER_SW_P016" (solid, remove dead copper, pour order 16): 1420,1395.38 1444.35,1371.79 1444.35,1340.79 1482.52,1340.79 1482.52,1372.93 1504,1394.41 1504,1547.35 1493.35,1558 1420,1558
GND on Signal Layer 2 "SIGNAL_LAYER_2_GND_P099" (solid, remove dead copper, pour order 99): 0,1781.5 2701,1781.5 2710.5,1791 2710.5,10 11.5,10 1.5,0 0,1.5
VIN on Signal Layer 2 "SIGNAL_LAYER_2_VIN_P060" (solid, remove dead copper, pour order 60): 2030,1223.27 2224.3,1223.27 2233.02,1223.27 2598.05,1223.27 2614.52,1239.74 2614.52,1386.74 2596.02,1405.24 1860,1405.24 1639.24,1405.24 1623,1389 1623,1237.29 1637.02,1223.27 1868.52,1223.27 2027.52,1223.27
VOUT on Signal Layer 2 "SIGNAL_LAYER_2_VOUT_P050" (solid, remove dead copper, pour order 50): 1155,1503 1176.63,1481.37 1176.63,1226.11 66.15,1226.11 58.52,1233.74 58.52,1488.02 73.5,1503
GND on Bottom Layer "BOTTOM_LAYER_GND_P101" (solid, remove dead copper, pour order 101): 0,1796.5 2705,1796.5 2710.5,1791 2710.5,0 8,0 8,1807.5
no net on Bottom Layer "BOTTOM_LAYER_NONET_P072" (solid, remove dead copper, pour order 72): 1877.64,1223.27 1872.96,1223.27 1865,1231.24 1865,1265.24 1875.5,1275.74 2008.5,1275.74 2018,1266.24 2018,1234.24 2007.93,1224.17
VIN_EMI_P on Bottom Layer "BOTTOM_LAYER_VIN_EMI_P_P078" (solid, remove dead copper, pour order 78): 2189.5,946.29 2061.5,946.29 2061.5,872.24 2189.5,872.24
GND on Signal Layer 1 "SIGNAL_LAYER_1_GND_P097" (solid, remove dead copper, pour order 97): 0,0 0,1796.5 2710.5,1796.5 2710.5,0 0,0

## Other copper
Bottom Layer:
  rectangle net VIN: 2061,973.74 2189.5,1057.24
  rectangle net VIN_EMI_P: 2061,865.74 2189.5,949.24
  pour cut-out: 1954.25,1125.8 2681.87,1124.59 2680.25,-36.8 1954.25,-36.8

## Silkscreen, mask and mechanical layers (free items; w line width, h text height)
Top Overlay:
  lines w10: 1066,352 1695.57,352 1695.57,566 1066,566 1066,352
  text "VOUT" at 287.5,1367 h36
  text "VIN" at 2470.5,1155 h36
  text "VOUT" at 287.5,1110.5 h36
  text "INJ" at 329.49,932.5 h36
  text "GND" at 323.49,665.5 h36
  text "EN" at 1890,634 h36
  text "GND" at 2472,606 h36
  text "1" at 1424.05,588.5 h30
  text "2" at 1525.29,587.5 h30
  text "3" at 1630.5,588.5 h30
  text "<JUMPER SETTING>" at 1152.73,507 h30
  text "GND" at 850.5,504 h36
  text "JP1:" at 1114,444.5 h30
  text "1&2 -> EN LOW" at 1253,439.5 h30
  text "BSR181 Rev.A" at 364,422 h70
  text "2&3 -> EN HIGH" at 1246.14,379.5 h30
  text "VEMI" at 2460.5,243 h36
Top Solder:
  rectangle: 1467.7,1453.5 1505.2,1558.5
  rectangle: 1240.5,1469 1278,1558
Bottom Solder:
  rectangle: 2061.5,872.24 2189.5,946.29
  rectangle: 2061,973.74 2189.5,1057.24
M1 Board Outline:
  the board outline again, w10
M2 Board Dimensions:
  rectangle: 125,-400 500,-275
  rectangle: 0,-275 125,-150
  lines w7: 0,-275 1000,-275 ; 125,-400 125,-150 ; 250,-400 250,-150 ; 500,-400 500,-150 ; 750,-400 750,-150 ; 0,-400 0,-150 1000,-150 1000,-400 0,-400
M5 Assembly Top:
  lines w10: -292,-930.17 6308,-930.17 ; -292,-726.83 6310,-726.83 ; -292,-523.5 -292,-1133.5 3713,-1133.5 6310,-1133.5 6310,-523.5 -291.5,-523.5 -291.5,-1133.5 1284,-1133.5 ; 2173,-1133.5 2173,-523.5 ; 3440,-726.83 3440,-523.5 ; 4280,-726.83 4280,-523.5 ; 4902,-1140 4902,-937.17
  text "COMPONENTS MARKED 'DNP' SHOULD NOT BE POPULATED." at 1153.5,-318.5 h60
  text "ASSEMBLY VARIANT:" at 1153,-434 h60
  text ".VariantName" at 2189,-434 h60
  text "PCB VIEWED FROM TOP SIDE" at -228.5,-655.67 h60
  text "BOARD #:" at 2248,-655.67 h60
  text ".PRJ_Number" at 2793.5,-655.67 h60
  text "REV:" at 3638,-655.67 h60
  text ".PCB_Rev" at 3929.5,-655.67 h60
  text "SVN REV:" at 4476,-655.67 h60
  text ".VersionControl_RevNumber" at 4982,-655.67 h60
  text "TID #:" at 2248,-859 h60
  text ".TID" at 2793.5,-859 h60
  text "PLOT NAME =" at -228.5,-1064.34 h60
  text ".plot_File_Name" at 577,-1064.34 h60
  text "GENERATED    :" at 2250,-1064.34 h60
  text ".Print_Date" at 3119.5,-1064.34 h60
  text ".Print_Time" at 3848.5,-1064.34 h60
  text "TEXAS INSTRUMENTS" at 5113,-1064.34 h60
M6 Assembly Bottom:
  lines w10: -292.5,-727.33 6309.5,-727.33 ; -290.5,-930.67 6309.5,-930.67 ; 1115.5,-1140.5 1115.5,-937.67 ; 1737.5,-727.33 1737.5,-524 ; 2577.5,-727.33 2577.5,-524 ; 3844.5,-1134 3844.5,-524 ; 4733.5,-1134 6309,-1134 6309,-524 -292.5,-524 -292.5,-1134 2304.5,-1134 6309.5,-1134 6309.5,-524
  text "COMPONENTS MARKED 'DNP' SHOULD NOT BE POPULATED." at 6102,-318 h60
  text ".VariantName" at 5058,-434 h60
  text "ASSEMBLY VARIANT:" at 6097,-434 h60
  text ".VersionControl_RevNumber" at 1035.5,-656.17 h60
  text "SVN REV:" at 1541.5,-656.17 h60
  text ".PCB_Rev" at 2088,-656.17 h60
  text "REV:" at 2379.5,-656.17 h60
  text ".PRJ_Number" at 3224,-656.17 h60
  text "BOARD #:" at 3769.5,-656.17 h60
  text "PCB VIEWED FROM BOTTOM SIDE" at 6246,-656.17 h60
  text ".TID" at 3224,-859.5 h60
  text "TID #:" at 3769.5,-859.5 h60
  text "TEXAS INSTRUMENTS" at 904.5,-1064.84 h60
  text ".Print_Time" at 2169,-1064.84 h60
  text ".Print_Date" at 2898,-1064.84 h60
  text "GENERATED    :" at 3767.5,-1064.84 h60
  text ".plot_File_Name" at 5440.5,-1064.84 h60
  text "PLOT NAME =" at 6246,-1064.84 h60
M9 Title Sheet:
  drawing of 57 lines, arcs and shapes, not listed
  text "1" at 739.84,8036.5 h70
  text "2" at 3235.5,8036.5 h70
  text "3" at 5724.84,8036.5 h70
  text "4" at 8231.51,8036.5 h70
  text "5" at 10730.5,8036.5 h70
  text "6" at 13235.5,8036.5 h70
  text "A" at -416.5,6893.5 h70
  text "A" at 14383.5,6893.5 h70
  text "B" at -416.5,4513.5 h70
  text "B" at 14383.5,4513.5 h70
  text "C" at -416.5,2138.5 h70
  text "C" at 14383.5,2138.5 h70
  text "PROJECT TITLE:" at 11343.5,277.5 h45
  text ".PRJ_Title" at 11393.5,144.17 h70
  text "DESIGNED FOR:" at 11343.5,-23.5 h45
  text ".PRJ_Customer" at 11393.5,-163.5 h70
  text "D" at -416.5,-231.5 h70
  text "D" at 14383.5,-231.5 h70
  text "FILE NAME:" at 11343.5,-323.5 h45
  text ".PCB_File_Name_No_Path" at 11393.5,-443.5 h70
  text "Texas Instruments (TI) and/or its licensors do not warrant the accuracy or completeness of this specification" at 6374,-605.34 h45
  text "ENGINEER:" at 11343.5,-613.5 h45
  text "LAYOUT BY:" at 12848.5,-613.5 h45
  text "or any information contained therein. TI and/or its licensors do not warrant that this design will meet" at 6329.01,-718 h45
  text ".PRJ_Engineer" at 11393.5,-768.49 h70
  text ".PCB_Layout" at 12899,-768.49 h70
  text "the specifications, will be suitable for your application or fit for any particular purpose, or will operate in" at 6329.01,-830.67 h45
  text "ALTIUM DESIGNER VERSION:" at 12848.5,-923.5 h45
  text "an implementation. TI and/or its licensors do not warrant that the design is production worthy. You should" at 6329.01,-943.33 h45
  text "completely validate and test your design implementation to confirm the system functionality for your application." at 6374,-1056 h45
  text ".print_Scale" at 11393.5,-1056.83 h70
  text ".Application_BuildNumber" at 12899,-1056.83 h70
  text "1" at 739.84,-1263.5 h70
  text "2" at 3235.5,-1263.5 h70
  text "3" at 5724.84,-1263.5 h70
  text "4" at 8231.51,-1263.5 h70
  text "5" at 10730.5,-1263.5 h70
  text "6" at 13235.5,-1263.5 h70
M10 Fab Notes:
  drawing of 173 lines, arcs and shapes, not listed
  text "DESIGN INFORMATION" at 12378.02,6201 h60
  text "MIN. TRACK WIDTH:" at 11733.46,6021 h60
  text "8" at 12829.7,6021 h60
  text "MIL" at 12984.46,6021 h60
  text "MIN. CLEARANCE:" at 11733.46,5889 h60
  text "0.2" at 12769.7,5889 h60
  text "mm" at 12984.46,5889 h60
  text "MIN. VIA PAD SIZE:" at 11733.46,5757 h60
  text "24" at 12799.71,5757 h60
  text "MIL" at 12984.46,5757 h60
  text "0.05mm (2MIL)" at 12428.46,5615.29 h60
  text "MINIMUM ANNULAR RING" at 11404.23,5611 h60
  text "EXTERNAL" at 13136.46,5611 h60
  text "PER" at 11604.23,5493 h60
  text "IPC-D-275 CLASS 2 LEVEL C" at 11824.23,5493 h60
  text "MIL, HOLES" at 13312.46,5380.71 h60
  text "+/-" at 12920,5380 h60
  text "+/-" at 13774,5380 h60
  text "REGISTRATION TOLERANCES:" at 11404.23,5375 h60
  text "METAL" at 12604,5375 h60
  text "5" at 13180.2,5375 h60
  text "3" at 14013.2,5375 h60
  text "MIL" at 14129.46,5375 h60
  text "+/-" at 13774,5262 h60
  text "HOLE SIZE TOLERANCE (UNLESS OTHERWISE SPECIFIED):" at 11404.23,5257 h60
  text "3" at 14013.2,5257 h60
  text "MIL" at 14129.46,5257 h60
  text "MATERIAL:" at 11329.46,5047.54 h60
  text "FR-4 High Tg" at 12315.9,4907.21 h60
  text "FR-408" at 11750.46,4898.64 h60
  text "OTHER" at 13238.46,4898.64 h60
  text "X" at 12161,4895 h60
  text "62 MIL (1.6mm) +/-10%" at 12070.56,4735.92 h60
  text "THICKNESS:" at 11404.23,4731.64 h60
  text "X" at 11942.4,4731.64 h60
  text "OTHER" at 13355.46,4731.64 h60
  text "TOLERANCE:" at 11404.23,4573.64 h60
  text "X" at 12243.53,4573.64 h60
  text "ANSI IPC-6012 TYPE 3 CLASS 2" at 12430.48,4573.64 h60
  text "OTHER +/-" at 12430.46,4417.64 h60
  text "BOW & TWIST:" at 11404.23,4260.64 h60
  text "X" at 12243.53,4260.64 h60
  text "ANSI IPC-6012 TYPE 3 CLASS 2" at 12430.48,4260.64 h60
  text "OTHER +/-" at 12430.46,4102.13 h60
  text "DRILLING:" at 11329.46,3963.64 h60
  text "REFERENCE:" at 11404.23,3846.64 h60
  text "X" at 12052.46,3846.64 h60
  text "AS SHOWN" at 12239.46,3846.64 h60
  text "X" at 12953.46,3846.64 h60
  text "NC_DRILL FILES" at 13090.46,3846.64 h60
  text "PTH COPPER THICKNESS:" at 11404.23,3688.64 h60
  text "X" at 12534.46,3688.64 h60
  text "20-30 um" at 12671.46,3688.64 h60
  text "OTHER" at 13388.46,3688.64 h60
  text "BOARD FINISH:" at 11329.46,3529.64 h60
  text "SILKSCREEN:" at 11484.68,3411.64 h60
  text "X" at 12433.46,3411.64 h60
  text "TOP" at 12559.46,3411.64 h60
  text "X" at 12943.46,3411.64 h60
  text "BOTTOM" at 13070.46,3411.64 h60
  text "SILKSCREEN COLOR:" at 11484.68,3244.64 h60
  text "X" at 12432.42,3244.64 h60
  text "WHITE" at 12559.46,3244.64 h60
  text "OTHER" at 13070.46,3244.64 h60
  text "X" at 12563.42,3085.44 h60
  text "GREEN" at 12690.46,3085.44 h60
  text "OTHER" at 13308.46,3085.44 h60
  text "SOLDER RESIST COLOR:" at 11484.68,3074.64 h60
  text "X" at 12563.42,2915.44 h60
  text "MATTE" at 12690.46,2915.44 h60
  text "SEMI-GLOSS" at 13308,2914.8 h60
  text "IMMERSION GOLD (ENIG)" at 12390.46,2726.92 h60
  text "ENEPIG" at 13728,2723.64 h60
  text "SURFACE FINISH:" at 11329.46,2722.64 h60
  text "X" at 12203.51,2722.64 h60
  text "IMM. TIN/SILVER OR EQUIV" at 11659,2565.64 h60
  text "OTHER" at 13090.46,2565.64 h60
  text "ARRAY/PANEL:" at 11329.46,2386.64 h60
  text "CUT AND TRIM PER M1 BOARD OUTLINE" at 12390.46,2382.35 h60
  text "N.C. ROUTE" at 12390.46,2230.64 h60
  text "X" at 13069.46,2230.64 h60
  text "V. SCORE" at 13256.46,2230.64 h60
  text "CERTIFICATION:" at 11329.46,2093.64 h60
  text "MATERIALS AND WORKMANSHIP FOR ALL PCBS" at 12054.46,2093.64 h60
  text "TO MEET OR EXCEED THE REQUIREMENTS OF:" at 12054.46,1995.64 h60
  text "X" at 11680.96,1859.13 h60
  text "ANSI IPC-A-600F CLASS ->" at 11819.96,1859.13 h60
  text "X" at 13459.02,1859.13 h60
  text "2" at 13577.96,1859.14 h60
  text "1" at 13262.96,1857.64 h60
  text "3" at 13931.96,1857.64 h60
  text "X" at 12495.02,1699.64 h60
  text "RoHS" at 12631.96,1699.64 h60
  text "OTHER" at 13276.36,1699.64 h60
  text "PER ORDER" at 13673.42,1699.64 h60
  text "ALL BOARDS MUST MEET OR EXCEED UL94-V0 REQUIREMENTS." at 11357,1534 h60
  text "PCB MUST BEAR THE UL94V-0 UL REGISTERED MATERIAL ID NUMBER" at 11357,1414 h60
  text "ADDITIONAL REQUIREMENTS:" at 11329.46,1240.64 h60
  text "MICROSECTION:" at 11404.23,1125.64 h60
  text "YES" at 12309.96,1125.64 h60
  text "REQUIRED" at 13171.46,969.49 h60
  text "BARE BOARD ELEC. TEST:" at 11404.23,966.64 h60
  text "NONE" at 12709.96,966.64 h60
  text "X" at 13044.46,966.64 h60
  text "PER ORDER" at 13763.46,966.64 h60
M11 Gerber Information:
  lines w10: -292,-930.17 6308,-930.17 ; -292,-726.83 6310,-726.83 ; -292,-523.5 -292,-1133.5 3713,-1133.5 6310,-1133.5 6310,-523.5 -291.5,-523.5 -291.5,-1133.5 1284,-1133.5 ; 2173,-1133.5 2173,-523.5 ; 3440,-726.83 3440,-523.5 ; 4280,-726.83 4280,-523.5 ; 4902,-1140 4902,-937.17
  text "ALL ARTWORK VIEWED FROM TOP SIDE" at -228.5,-655.67 h60
  text "BOARD #:" at 2248,-655.67 h60
  text ".PRJ_Number" at 2793.5,-655.67 h60
  text "REV:" at 3638,-655.67 h60
  text ".PCB_Rev" at 3929.5,-655.67 h60
  text "SVN REV:" at 4476,-655.67 h60
  text ".VersionControl_RevNumber" at 4982,-655.67 h60
  text "LAYER NAME =" at -228.5,-858.49 h60
  text "TID #:" at 2248,-859 h60
  text ".TID" at 2793.5,-859 h60
  text "PLOT NAME =" at -228.5,-1064.34 h60
  text ".plot_File_Name" at 577,-1064.34 h60
  text "GENERATED    :" at 2250,-1064.34 h60
  text ".Print_Date" at 3119.5,-1064.34 h60
  text ".Print_Time" at 3848.5,-1064.34 h60
  text "TEXAS INSTRUMENTS" at 5113,-1064.34 h60
M12 Stackup:
  drawing of 269 lines, arcs and shapes, not listed
  text "Layer" at 2707.55,6065 h60
  text "Name" at 3117.47,6065 h60
  text "Material" at 4057.21,6065 h60
  text "Thickness" at 4916.97,6065 h60
  text "Constant" at 5566.81,6065 h60
  text "Board Layer Stack" at 6136.67,6065 h60
  text "1" at 2707.55,5945 h60
  text "Top Overlay" at 3117.47,5945 h60
  text "2" at 2707.55,5825 h60
  text "Top Solder" at 3117.47,5825 h60
  text "Solder Resist" at 4057.21,5825 h60
  text "0.40mil" at 4916.97,5825 h60
  text "3.5" at 5566.81,5825 h60
  text "3" at 2707.55,5705 h60
  text "Top Layer" at 3117.47,5705 h60
  text "Copper" at 4057.21,5705 h60
  text "2.80mil" at 4916.97,5705 h60
  text "4" at 2707.55,5585 h60
  text "Dielectric1" at 3117.47,5585 h60
  text "FR-4 High Tg" at 4057.21,5585 h60
  text "10.00mil" at 4916.97,5585 h60
  text "4.8" at 5566.81,5585 h60
  text "5" at 2707.55,5465 h60
  text "Signal Layer 1" at 3117.47,5465 h60
  text "Copper" at 4057.21,5465 h60
  text "1.42mil" at 4916.97,5465 h60
  text "6" at 2707.55,5345 h60
  text "Dielectric 2" at 3117.47,5345 h60
  text "FR-4 High Tg" at 4057.21,5345 h60
  text "32.00mil" at 4916.97,5345 h60
  text "4.2" at 5566.81,5345 h60
  text "7" at 2707.55,5225 h60
  text "Signal Layer 2" at 3117.47,5225 h60
  text "Copper" at 4057.21,5225 h60
  text "1.42mil" at 4916.97,5225 h60
  text "8" at 2707.55,5105 h60
  text "Dielectric 3" at 3117.47,5105 h60
  text "FR-4 High Tg" at 4057.21,5105 h60
  text "10.00mil" at 4916.97,5105 h60
  text "4.2" at 5566.81,5105 h60
  text "9" at 2707.55,4985 h60
  text "Bottom Layer" at 3117.47,4985 h60
  text "Copper" at 4057.21,4985 h60
  text "2.80mil" at 4916.97,4985 h60
  text "10" at 2707.55,4865 h60
  text "Bottom Solder" at 3117.47,4865 h60
  text "Solder Resist" at 4057.21,4865 h60
  text "0.40mil" at 4916.97,4865 h60
  text "3.5" at 5566.81,4865 h60
Drill Drawing:
  circle w10: c2734.99,4398.15 r27.63
  lines w10: 2707.36,4246.2 2762.62,4246.2 2762.62,4301.45 2707.36,4301.45 2707.36,4246.2 ; 2707.36,4550.09 2762.62,4550.09 2734.99,4494.84 2707.36,4550.09 ; 2707.36,4632.97 2721.18,4632.97 2734.99,4619.16 2748.8,4632.97 2762.62,4632.97 2748.8,4646.79 2762.62,4660.6 2748.8,4660.6 2734.99,4674.41 2721.18,4660.6 2707.36,4660.6 2721.18,4646.79 2707.36,4632.97
  lines w12: 2657.27,4208.9 9800.26,4208.9 ; 2657.27,4706.18 9800.26,4706.18 ; 2995.14,4084.58 2995.14,4830.5 ; 3327.14,4084.58 3327.14,4830.5 ; 3963.7,4084.58 3963.7,4830.5 ; 4222.84,4084.58 4222.84,4830.5 ; 4598,4084.58 4598,4830.5 ; 5322.33,4084.58 5322.33,4830.5 ; 5851.47,4084.58 5851.47,4830.5 ; 6154.76,4084.58 6154.76,4830.5 ; 6551.43,4084.58 6551.43,4830.5 ; 6990.27,4084.58 6990.27,4830.5 ; 7410.18,4084.58 7410.18,4830.5 ; 8037.02,4084.58 8037.02,4830.5 ; 8647.68,4084.58 8647.68,4830.5 ; 9085.44,4084.58 9085.44,4830.5 ; 2657.27,4084.58 9800.26,4084.58 9800.26,4830.5 2657.27,4830.5 2657.27,4084.58
  text "Symbol" at 2731.87,4743.48 h72
  text "Quantity" at 3032.43,4743.48 h72
  text "Finished Hole Size" at 3364.43,4743.48 h72
  text "Plated" at 4001,4743.48 h72
  text "Hole Type" at 4260.14,4743.48 h72
  text "Drill Layer Pair" at 4635.29,4743.48 h72
  text "Hole Tolerance" at 5359.63,4743.48 h72
  text "Via/Pad" at 5888.76,4743.48 h72
  text "Pad Shape" at 6192.06,4743.48 h72
  text "Template" at 6588.73,4743.48 h72
  text "Description" at 7027.57,4743.48 h72
  text "Hole Tolerance (+)" at 7447.48,4743.48 h72
  text "Hole Tolerance (-)" at 8074.32,4743.48 h72
  text "Hole Length" at 8684.97,4743.48 h72
  text "Routed Path Length" at 9122.74,4743.48 h72
  text "44" at 3032.43,4619.16 h60
  text "16.00mil (0.406mm)" at 3364.43,4619.16 h60
  text "PTH" at 4001,4619.16 h60
  text "Round" at 4260.14,4619.16 h60
  text "Top Layer - Bottom Layer" at 4635.29,4619.16 h60
  text "Via" at 5888.76,4619.16 h60
  text "Rounded" at 6192.06,4619.16 h60
  text "v81h41m0mx0" at 6588.73,4619.16 h60
  text "-" at 8684.97,4619.16 h60
  text "-" at 9122.74,4619.16 h60
  text "3" at 3032.43,4494.84 h60
  text "40.00mil (1.016mm)" at 3364.43,4494.84 h60
  text "PTH" at 4001,4494.84 h60
  text "Round" at 4260.14,4494.84 h60
  text "Top Layer - Bottom Layer" at 4635.29,4494.84 h60
  text "Pad" at 5888.76,4494.84 h60
  text "(Mixed)" at 6192.06,4494.84 h60
  text "(Mixed)" at 6588.73,4494.84 h60
  text "-" at 8684.97,4494.84 h60
  text "-" at 9122.74,4494.84 h60
  text "4" at 3032.43,4370.52 h60
  text "63.00mil (1.600mm)" at 3364.43,4370.52 h60
  text "PTH" at 4001,4370.52 h60
  text "Round" at 4260.14,4370.52 h60
  text "Top Layer - Bottom Layer" at 4635.29,4370.52 h60
  text "Pad" at 5888.76,4370.52 h60
  text "Rounded" at 6192.06,4370.52 h60
  text "c221h160" at 6588.73,4370.52 h60
  text "-" at 8684.97,4370.52 h60
  text "-" at 9122.74,4370.52 h60
  text "5" at 3032.43,4246.2 h60
  text "98.43mil (2.500mm)" at 3364.43,4246.2 h60
  text "PTH" at 4001,4246.2 h60
  text "Round" at 4260.14,4246.2 h60
  text "Top Layer - Bottom Layer" at 4635.29,4246.2 h60
  text "Pad" at 5888.76,4246.2 h60
  text "Rounded" at 6192.06,4246.2 h60
  text "c350h250" at 6588.73,4246.2 h60
  text "-" at 8684.97,4246.2 h60
  text "-" at 9122.74,4246.2 h60
  text "56 Total" at 3032.43,4121.88 h60
M17 Embedded Cavity:
  text ".Layer_Name" at 577,-858.49 h60
M18 Embedded Assembly:
  text ".Layer_Name" at 577,-858.49 h60
M19 Embedded Keepout:
  text ".Layer_Name" at 577,-858.49 h60

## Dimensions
0,0 to 0,1796.5 on M2 Board Dimensions
0,-400 to 1000,-400 on M2 Board Dimensions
